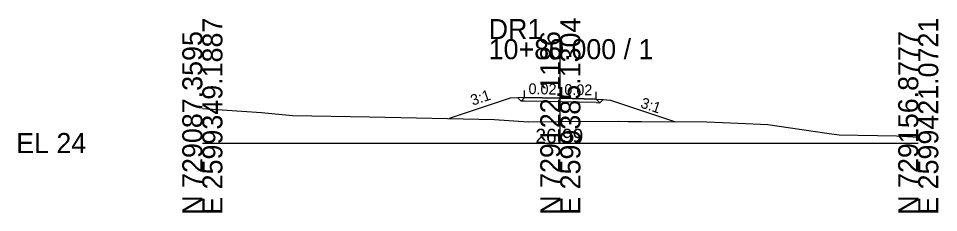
# Model space of a CAD drawing. Extents: x -26 to 1162, y -10 to 9515.
# Drawn here: x -25.7 to 102.8, y 3990.3 to 4017.4 of the extents above; entities that cross this region are included whole.
import ezdxf

# ---------------------------------------------------------------- set-up
doc = ezdxf.new("R2010")
doc.units = 0
for name, color, linetype in [('Exist Cross Section Cell', 7, 'Continuous'), ('Exist XS Center Line Elevation Label', 7, 'Continuous'), ('Exist XS Ground Line', 7, 'Continuous'), ('Prop XS Ditch Slope Text', 7, 'Continuous'), ('Prop XS Dump Level', 7, 'Continuous'), ('Prop XS EOT Tick Mark', 7, 'Continuous'), ('Prop XS Finish Grade', 7, 'Continuous'), ('Prop XS Finish Grade Earthwork', 7, 'Continuous'), ('Prop XS Finish Grade Pavement', 7, 'Continuous'), ('Prop XS Pvmt Edge Slope', 7, 'Continuous'), ('Prop XS SE Text', 7, 'Continuous'), ('Prop XS Subgrade Earthwork', 7, 'Continuous')]:
    doc.layers.add(name, color=color, linetype=linetype)

msp = doc.modelspace()

# ---------------------------------------------------------------- linework, layer by layer
at = {"layer": 'Exist Cross Section Cell'}
for p, q in [((50, 4000), (50, 4014.49)), ((0, 4000), (50, 4000)), ((50, 4000), (100, 4000))]:
    msp.add_line(p, q, dxfattribs=at)
at = {"layer": 'Exist XS Ground Line'}
msp.add_lwpolyline([(0, 4004.83), (8.27, 4004.24), (12.57, 4003.85), (23.34, 4003.67), (40.8, 4003.27), (45.5, 4002.96), (50, 4002.99), (58.18, 4003.04), (59.46, 4003.02), (61.32, 4002.99), (70.48, 4002.94), (74.83, 4002.76), (79, 4002.59), (87.23, 4001.4), (88.94, 4001.13), (96.98, 4000.99), (100, 4000.8)], dxfattribs=at)
at = {"layer": 'Prop XS Dump Level'}
for p, q in [((50, 4006.24), (45, 4006.34)), ((45, 4006.34), (50, 4006.24)), ((55, 4006.14), (50, 4006.24)), ((50, 4006.24), (55, 4006.14))]:
    msp.add_line(p, q, dxfattribs=at)
at = {"layer": 'Prop XS EOT Tick Mark'}
for p, q in [((45, 4006.34), (45, 4007.34)), ((55, 4006.14), (55, 4007.14))]:
    msp.add_line(p, q, dxfattribs=at)
at = {"layer": 'Prop XS Finish Grade'}
for p, q in [((45, 4006.34), (44.06, 4006.3)), ((55, 4006.14), (55.98, 4006.06))]:
    msp.add_line(p, q, dxfattribs=at)
at = {"layer": 'Prop XS Finish Grade Earthwork'}
for p, q in [((43, 4006.26), (34.46, 4003.41)), ((44.06, 4006.3), (43, 4006.26)), ((55.98, 4006.06), (57, 4005.98)), ((57, 4005.98), (66.07, 4002.96))]:
    msp.add_line(p, q, dxfattribs=at)
at = {"layer": 'Prop XS Finish Grade Pavement'}
for p, q in [((45, 4006.34), (50, 4006.24)), ((50, 4006.24), (55, 4006.14))]:
    msp.add_line(p, q, dxfattribs=at)
at = {"layer": 'Prop XS Pvmt Edge Slope'}
for p, q in [((44.06, 4006.3), (44.51, 4005.85)), ((45, 4006.34), (44.51, 4005.85)), ((55, 4006.14), (55.51, 4005.63)), ((55.98, 4006.06), (55.51, 4005.63))]:
    msp.add_line(p, q, dxfattribs=at)
at = {"layer": 'Prop XS Subgrade Earthwork'}
for p, q in [((44.51, 4005.85), (44.06, 4006.3)), ((44.51, 4005.85), (44.06, 4006.3)), ((45, 4005.84), (44.51, 4005.85)), ((50, 4005.74), (45, 4005.84)), ((55, 4005.64), (50, 4005.74)), ((55, 4005.64), (55.51, 4005.63)), ((55.51, 4005.63), (55.98, 4006.06)), ((55.51, 4005.63), (55.98, 4006.06))]:
    msp.add_line(p, q, dxfattribs=at)

# ---------------------------------------------------------------- texts
at = {"layer": 'Exist Cross Section Cell'}
for s, p in [('E 2599349.1887', (2.8, 3990)), ('E 2599385.1304', (52.8, 3990)), ('E 2599421.0721', (102.8, 3990)), ('N 729087.3595', (0, 3990)), ('N 729122.1186', (50, 3990)), ('N 729156.8777', (100, 3990))]:
    msp.add_text(s, height=2.8, rotation=90, dxfattribs=at).set_placement(p)
for s, p in [('DR1', (40, 4014.49)), ('10+80.000 / 1', (40, 4011.69)), ('EL 24', (-26, 3998.6))]:
    msp.add_text(s, height=2.8, dxfattribs=at).set_placement(p)
at = {"layer": 'Exist XS Center Line Elevation Label'}
msp.add_text('26.99', height=2, dxfattribs=at).set_placement((46.52, 3999.99))
at = {"layer": 'Prop XS Ditch Slope Text'}
for rotation, p in [(18.4349, (37.76, 4005.2)), (341.5883, (61.1, 4004.98))]:
    msp.add_text('3:1', height=1.5, rotation=rotation, dxfattribs=at).set_placement(p)
at = {"layer": 'Prop XS Dump Level'}
for p in [(43, 4006.22), (57, 4005.94)]:
    msp.add_text('Case1', height=0.04, dxfattribs=at).set_placement(p)
at = {"layer": 'Prop XS SE Text'}
for p in [(45.55, 4006.83), (50.55, 4006.73)]:
    msp.add_text('0.02', height=1.5, rotation=358.8542, dxfattribs=at).set_placement(p)

doc.saveas('drawing.dxf')
